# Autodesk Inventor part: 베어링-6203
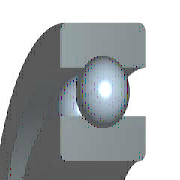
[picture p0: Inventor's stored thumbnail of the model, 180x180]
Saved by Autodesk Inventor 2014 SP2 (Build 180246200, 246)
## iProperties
IsCustomPart: 0
Created: 2016-05
Part Number: 베어링-6203
Material: 강, 연강
Description: 깊은 그루브 볼 베어링
Document SubType Name: Modeling
Standard: KS B 2023
Designer: mduedu
Standards Organization: KS
Language: ko-KR
Size Designation: 6203 - 17 x 40 x 12
Categories: <MemberInstance><Categories><Category DisplayName="샤프트 부품" InternalName="7f7aeb1f-a693-4053-b835-cee3144e0d98" Mnemonic="SHFT"><Category DisplayName="베어링" Inter
Density: 1 g/cm^3
Appearance: 노란색
Author: mduedu
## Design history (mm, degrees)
sketch "스케치" dims "d0" = 5.98 (= -0.26 x WD + 0.26 x BD)
  geometry: L1 (3.01, 14.25)-(8.99, 14.25); L2 (6, 14.25)-(6, 11.26); L3 (6, 14.25)-(6, 17.24); L4 (3.778, 12.249)-(0, 12.249); L5 (0, 8.5)-(12, 8.5); L6 (3.778, 16.251)-(0, 16.251); L7 (0, 20)-(12, 20); L8 (12, 8.5)-(12, 12.249); L9 (8.222, 12.249)-(12, 12.249); L10 (8.222, 16.251)-(12, 16.251); L11 (12, 20)-(12, 16.251); L12 (-1.4, 0)-(8.4, 0) reference; L13 (0, -0.3)-(0, 5.3) reference
  constraints: 22 end point, 4 point on line, 2 collinear, 2 perpendicular, 2 symmetric about line, 1 midpoint, 1 parallel, 14 other
  dimensions: "d9" = 17 diameter of L5 L12 (= WD); "d11" = 40 diameter of L7 L12 (= BD); "d12" = 12 distance between parallel lines of L8 L13 (= KB); "d13" = 24.498 diameter of L9 L12 (= 0.326 x BD + 0.674 x WD)
revolve "본체" stored, may be unused: angle "d6" = 90 deg
revolve "볼" stored, may be unused: angle "d7" = 90 deg
pattern_circular "IDS_ARRAYBALL[SIMPL:T]" dims angle "d3" = 360 deg
body "Solid1"
fillet "모깎기1" dims "d1" = 0.6 (= KRS)
other parameters: "WD" = 17 [user parameter; used in 5 equation terms], "BD" = 40 [user parameter; used in 5 equation terms], "KB" = 12 [user parameter; used in 1 equation term], "KRS" = 0.6 [user parameter; used in 1 equation term], "d4" = 0, "d5" = 0, "d8" = 0, "d14" = 0, "d15" = 0, "BBA" = 0 [user parameter], "BC0" = 4750000 [user parameter], "BC" = 9560000 [user parameter], "WR" = 8.5 (= 0.5 x WD) [user parameter]
